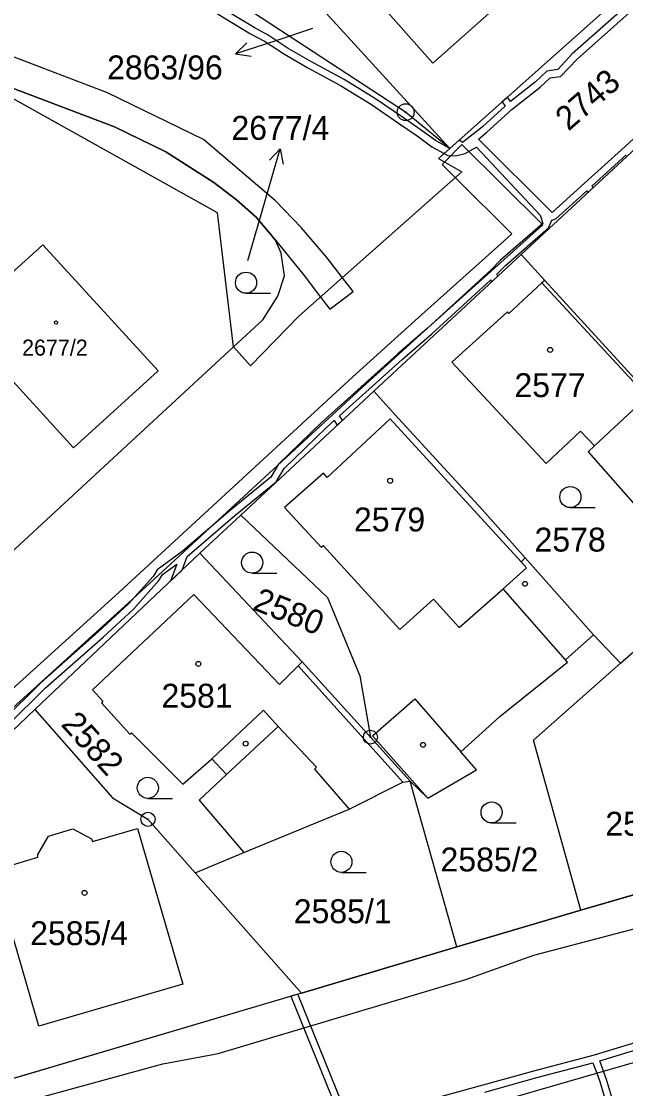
# Model space of a CAD drawing. Extents: x -644096 to -634268, y -1141430 to -1133463.
# Drawn here: x -639634.9 to -639592, y -1138632.6 to -1138556.7 of the extents above; entities that cross this region are included whole.
import ezdxf

# ---------------------------------------------------------------- set-up
doc = ezdxf.new("R2010")
doc.units = 0
for name, color, linetype in [('_CIVIL_CONSTRUCTION', 7, 'Continuous'), ('B_Hranice _3D', 7, 'Continuous'), ('M_Svah_Nasyp', 7, 'Continuous'), ('M_Svah_Zarez', 7, 'Continuous'), ('svrsek_osa_sjezdy', 7, 'Continuous'), ('svrsek_osa_terminal_VRT', 7, 'Continuous'), ('svrsek_osa_VRT', 7, 'Continuous'), ('svrsek_popisy_VRT', 7, 'Continuous'), ('terminal_VRT', 7, 'Continuous')]:
    doc.layers.add(name, color=color, linetype=linetype)

msp = doc.modelspace()

# ---------------------------------------------------------------- linework, layer by layer
at = {"layer": '_CIVIL_CONSTRUCTION'}
for centre, radius in [((-639607.63, -1138563.15), 0.6), ((-639607.63, -1138563.15), 0.0364), ((-639610.13, -1138607.58), 0.5), ((-639610.13, -1138607.58), 0.0303), ((-639625.94, -1138613.42), 0.5), ((-639625.94, -1138613.42), 0.0303)]:
    msp.add_circle(centre, radius, dxfattribs=at)
at = {"layer": 'B_Hranice _3D'}
for points in [[(-639658.11, -1138556.23), (-639639.64, -1138559.9), (-639628.33, -1138564.19), (-639624.68, -1138565.97), (-639621.26, -1138568.15), (-639619.65, -1138569.37), (-639618.26, -1138570.61), (-639616.87, -1138572.24), (-639614.84, -1138574.75), (-639613.67, -1138576.29), (-639613.01, -1138577.16), (-639611.37, -1138575.9), (-639612.12, -1138574.92), (-639613.24, -1138573.47), (-639615.04, -1138571.37), (-639616.88, -1138569.46), (-639622, -1138565.1), (-639628.82, -1138561.77), (-639635.75, -1138559.11), (-639643.38, -1138556.94), (-639667.92, -1138552.22)], [(-639578.14, -1138552.92), (-639582.84, -1138557.07), (-639585.31, -1138559.34), (-639587.95, -1138561.84), (-639592.29, -1138565.82), (-639594.91, -1138568.2), (-639597.21, -1138570.28), (-639602.45, -1138565.07), (-639601.85, -1138564.58), (-639600.07, -1138562.94), (-639598.08, -1138561.38), (-639597.36, -1138560.7), (-639596.62, -1138560.6), (-639595.44, -1138559.37), (-639590.01, -1138554.53)], [(-639590.43, -1138554.23), (-639595.8, -1138559.01), (-639596.82, -1138560.12), (-639597.59, -1138560.22)], [(-639621.62, -1138555.77), (-639618.65, -1138557.57), (-639617.65, -1138558.1), (-639616.23, -1138559.03), (-639614.57, -1138560), (-639612.27, -1138561.26), (-639610.06, -1138562.61), (-639608.13, -1138563.93), (-639606.81, -1138564.83), (-639605.76, -1138565.6), (-639604.89, -1138566.09), (-639604.63, -1138566.23), (-639604.09, -1138566.24), (-639603.4, -1138566.09), (-639602.6, -1138565.64), (-639598.06, -1138570.46), (-639597.89, -1138571.07), (-639600.88, -1138573.68), (-639601.56, -1138574.36), (-639606.1, -1138578.53), (-639608.21, -1138580.35), (-639613.61, -1138585.22), (-639616.67, -1138588.16), (-639617.22, -1138589.09), (-639620.08, -1138591.44)], [(-639597.59, -1138560.22), (-639598.4, -1138561), (-639600.18, -1138562.39), (-639600.4, -1138562.09), (-639600.78, -1138562.42), (-639600.56, -1138562.72), (-639602.17, -1138564.2), (-639603.59, -1138565.3), (-639603.82, -1138565.13), (-639604.49, -1138565.73), (-639605.5, -1138565.16), (-639606.53, -1138564.43), (-639607.85, -1138563.51), (-639609.78, -1138562.19), (-639612.01, -1138560.82), (-639614.33, -1138559.56), (-639615.97, -1138558.61), (-639617.39, -1138557.68), (-639618.39, -1138557.13), (-639621.36, -1138555.35)], [(-639641.76, -1138611.1), (-639627.33, -1138598.04), (-639617.93, -1138589.36), (-639610.71, -1138582.71), (-639606.3, -1138578.69), (-639599.97, -1138573.03), (-639597.88, -1138571.16), (-639603.63, -1138565.45), (-639604.86, -1138566.7), (-639605.03, -1138566.87), (-639604.09, -1138567.81), (-639600.08, -1138571.8), (-639600.63, -1138572.29), (-639606.96, -1138577.95), (-639611.39, -1138581.97), (-639618.61, -1138588.62), (-639628.01, -1138597.3)], [(-639635.92, -1138606.75), (-639633.22, -1138604.07), (-639629.13, -1138600.48), (-639626.97, -1138598.47), (-639625.17, -1138596.45), (-639624.91, -1138596.02), (-639623.89, -1138595.28), (-639624.34, -1138596.49), (-639623.51, -1138595.7), (-639623.15, -1138594.74), (-639619.76, -1138591.82), (-639616.84, -1138589.43), (-639616.27, -1138588.48), (-639613.27, -1138585.58), (-639612.7, -1138585.07), (-639612.49, -1138585.4), (-639612.11, -1138585.05), (-639612.32, -1138584.73), (-639607.87, -1138580.73), (-639605.76, -1138578.91), (-639601.58, -1138575.06), (-639601.56, -1138575.24), (-639601.11, -1138574.82), (-639601.13, -1138574.63), (-639600.54, -1138574.04), (-639597.47, -1138571.37), (-639597.25, -1138570.82), (-639596.95, -1138570.72), (-639594.76, -1138568.75), (-639594.67, -1138568.85), (-639594.3, -1138568.51), (-639594.39, -1138568.41), (-639591.95, -1138566.18)], [(-639636.06, -1138634.3), (-639634.04, -1138633.31), (-639624.89, -1138630.8), (-639620.95, -1138630.07), (-639603.36, -1138624.81), (-639598.51, -1138623.07), (-639582.86, -1138618.95), (-639554.59, -1138610.51), (-639542.49, -1138606.71), (-639532.13, -1138603.17), (-639523.43, -1138599.72), (-639503.23, -1138590.28), (-639493.08, -1138586.17)], [(-639498.99, -1138586.56), (-639513.43, -1138593.01), (-639522.91, -1138596.98), (-639524.57, -1138597.67), (-639533.41, -1138601.31), (-639536.57, -1138602.39), (-639543.26, -1138604.42), (-639551.43, -1138607.04), (-639555.39, -1138608.28), (-639566.35, -1138611.47), (-639568.99, -1138612.24), (-639574.69, -1138613.9), (-639595.17, -1138619.87), (-639603.99, -1138622.49), (-639615.04, -1138625.77), (-639637.75, -1138632.51)], [(-639620.08, -1138591.44), (-639623.52, -1138594.39), (-639625.29, -1138595.68), (-639625.57, -1138596.15), (-639627.33, -1138598.11), (-639629.47, -1138600.1), (-639633.56, -1138603.71), (-639636.26, -1138606.39)], [(-639628.01, -1138597.3), (-639642.44, -1138610.36), (-639646.98, -1138614.51)], [(-639544.79, -1138615.76), (-639545.43, -1138616.39), (-639546.02, -1138616.77), (-639546.4, -1138616.74), (-639546.76, -1138616.71), (-639550.78, -1138618), (-639554.66, -1138619.05), (-639560.3, -1138620.49), (-639567.96, -1138622.71), (-639573.14, -1138624.16), (-639577.64, -1138625.42), (-639579.66, -1138625.97), (-639585.28, -1138627.53), (-639588.31, -1138628.43), (-639590.19, -1138628.95), (-639594.23, -1138630.18), (-639598.45, -1138631.29), (-639602.15, -1138632.33), (-639607.83, -1138633.88)], [(-639592.51, -1138634.76), (-639593.35, -1138631.91), (-639593.56, -1138631.33), (-639593.84, -1138630.58), (-639590.05, -1138629.43), (-639588.41, -1138628.98), (-639588.19, -1138629.78), (-639588.04, -1138630.3), (-639587.1, -1138633.22)], [(-639602.01, -1138632.81), (-639598.31, -1138631.77), (-639594.32, -1138630.72), (-639594.05, -1138631.47), (-639593.83, -1138632.07), (-639592.99, -1138634.89)]]:
    msp.add_lwpolyline(points, dxfattribs=at)
msp.add_lwpolyline([(-639615.78, -1138625.99), (-639610.66, -1138638.62), (-639610.2, -1138638.43), (-639615.3, -1138625.85)], close=True, dxfattribs=at)
at = {"layer": 'M_Svah_Nasyp'}
for p, q in [((-639612.46, -1138552.02), (-639605.69, -1138559.66)), ((-639605.69, -1138559.66), (-639599.67, -1138554.3)), ((-639597.95, -1138575.27), (-639589.7, -1138584.2)), ((-639591.47, -1138584.3), (-639594.21, -1138586.86)), ((-639608.73, -1138584.94), (-639613.21, -1138589.13)), ((-639599.42, -1138595.11), (-639608.73, -1138584.94)), ((-639613.47, -1138588.8), (-639616.23, -1138591.24)), ((-639613.21, -1138589.13), (-639613.47, -1138588.8)), ((-639616.23, -1138591.24), (-639613.63, -1138594.07)), ((-639613.63, -1138594.07), (-639613.5, -1138593.95)), ((-639599.13, -1138594.84), (-639599.42, -1138595.11)), ((-639599.42, -1138595.11), (-639599.03, -1138595.54)), ((-639600.7, -1138597.04), (-639599.03, -1138595.54)), ((-639596.28, -1138602.07), (-639600.7, -1138597.04)), ((-639615.26, -1138602.51), (-639607.84, -1138610.78)), ((-639621.39, -1138609.13), (-639617.74, -1138605.67)), ((-639617.74, -1138605.67), (-639616.68, -1138606.81)), ((-639616.68, -1138606.81), (-639620.36, -1138610.24)), ((-639616.68, -1138606.81), (-639613.96, -1138609.72)), ((-639609.99, -1138607.49), (-639606.06, -1138611.91)), ((-639613.96, -1138609.72), (-639614.11, -1138609.86)), ((-639614.11, -1138609.86), (-639611.65, -1138612.69))]:
    msp.add_line(p, q, dxfattribs=at)
for points in [[(-639605.64, -1138597.77), (-639608.05, -1138599.92), (-639613.5, -1138593.95)], [(-639605.64, -1138597.77), (-639603.82, -1138599.78), (-639600.7, -1138597.04)], [(-639609.99, -1138607.49), (-639606.97, -1138604.85), (-639603.7, -1138608.63)]]:
    msp.add_lwpolyline(points, dxfattribs=at)
at = {"layer": 'M_Svah_Zarez'}
for centre, radius in [((-639632.475, -1138578.109), 0.117), ((-639597.367, -1138580.049), 0.175), ((-639608.727, -1138589.349), 0.175), ((-639599.147, -1138596.679), 0.175), ((-639622.357, -1138602.369), 0.175), ((-639618.997, -1138608.039), 0.175), ((-639606.397, -1138608.129), 0.175), ((-639630.447, -1138618.649), 0.175)]:
    msp.add_circle(centre, radius, dxfattribs=at)
at = {"layer": 'svrsek_osa_sjezdy'}
for p, q in [((-639618.973, -1138576.02), (-639617.223, -1138576.02)), ((-639595.923, -1138591.26), (-639594.173, -1138591.26)), ((-639618.533, -1138595.92), (-639616.783, -1138595.92)), ((-639625.953, -1138611.93), (-639624.203, -1138611.93)), ((-639601.523, -1138613.68), (-639599.773, -1138613.68)), ((-639612.193, -1138617.19), (-639610.443, -1138617.19))]:
    msp.add_line(p, q, dxfattribs=at)
for centre in [(-639618.973, -1138575.27), (-639595.923, -1138590.51), (-639618.533, -1138595.17), (-639625.953, -1138611.18), (-639601.523, -1138612.93), (-639612.193, -1138616.44)]:
    msp.add_circle(centre, 0.75, dxfattribs=at)
at = {"layer": 'svrsek_osa_terminal_VRT'}
msp.add_arc((-642050.261, -1145189.597), 8802.25, 41.4131519, 75.3170489, dxfattribs=at)
at = {"layer": 'svrsek_popisy_VRT'}
for p, q in [((-639614.26, -1138557.21), (-639616.86, -1138558.07)), ((-639616.86, -1138558.07), (-639619.714, -1138558.997)), ((-639619.714, -1138558.997), (-639618.916, -1138558.212)), ((-639619.714, -1138558.997), (-639618.607, -1138559.164)), ((-639617.37, -1138568.63), (-639616.543, -1138565.745)), ((-639616.543, -1138565.745), (-639617.3, -1138566.57)), ((-639616.543, -1138565.745), (-639616.338, -1138566.846)), ((-639618.84, -1138573.7), (-639617.37, -1138568.63))]:
    msp.add_line(p, q, dxfattribs=at)
at = {"layer": 'terminal_VRT'}
for p, q in [((-639615.47, -1138553.71), (-639604.49, -1138565.73)), ((-639604.49, -1138565.73), (-639593.46, -1138555.9)), ((-639585.65, -1138560.49), (-639599.43, -1138573.26)), ((-639599.43, -1138573.26), (-639609.9, -1138582.99)), ((-639599.43, -1138573.26), (-639597.73, -1138575.11)), ((-639637.64, -1138596.27), (-639619.86, -1138579.83)), ((-639609.9, -1138582.99), (-639619.35, -1138591.8)), ((-639619.35, -1138591.8), (-639622.25, -1138594.51)), ((-639622.25, -1138594.51), (-639633.98, -1138605.62)), ((-639622.25, -1138594.51), (-639614.98, -1138602.23)), ((-639592.36, -1138602.33), (-639588.9, -1138599.27)), ((-639594.28, -1138600.3), (-639592.36, -1138602.33)), ((-639614.98, -1138602.23), (-639610.13, -1138607.58)), ((-639645.23, -1138616.27), (-639633.98, -1138605.62)), ((-639610.13, -1138607.58), (-639607.3, -1138610.71)), ((-639595.17, -1138619.87), (-639574.69, -1138613.9)), ((-639622.58, -1138617.23), (-639619.12, -1138615.79)), ((-639622.58, -1138617.23), (-639615.04, -1138625.77)), ((-639603.99, -1138622.49), (-639595.17, -1138619.87)), ((-639615.04, -1138625.77), (-639603.99, -1138622.49)), ((-639615.04, -1138625.77), (-639637.75, -1138632.51))]:
    msp.add_line(p, q, dxfattribs=at)
for points in [[(-639604.49, -1138565.73), (-639607.63, -1138563.15), (-639619.59, -1138555.32)], [(-639619.86, -1138579.83), (-639621, -1138570.3), (-639639.64, -1138559.9)], [(-639619.86, -1138579.83), (-639617.78, -1138577.9), (-639616.7, -1138576.23), (-639616.24, -1138574.78), (-639616.47, -1138573.18), (-639616.87, -1138572.24), (-639618.26, -1138570.61), (-639619.65, -1138569.37), (-639621.26, -1138568.15), (-639624.68, -1138565.97), (-639628.33, -1138564.19), (-639639.64, -1138559.9)], [(-639420.67, -1138563.16), (-639420.77, -1138562.15), (-639453.01, -1138577.21), (-639479.01, -1138589.5), (-639514.61, -1138604.87), (-639530.15, -1138610.96), (-639554.65, -1138619.67), (-639587.03, -1138629.44), (-639631.61, -1138642.35), (-639671.45, -1138653.1), (-639676.11, -1138654.27)], [(-639604.49, -1138565.73), (-639605.29, -1138566.45), (-639603.63, -1138567.4), (-639615.21, -1138577.65), (-639618.66, -1138581.17), (-639619.86, -1138579.83)], [(-639638.03, -1138582.1), (-639642.04, -1138577.68), (-639639.22, -1138575.12), (-639637.93, -1138576.65), (-639633.41, -1138572.58), (-639625.21, -1138581.54), (-639631.23, -1138587.01), (-639636.77, -1138580.95), (-639638.03, -1138582.1)], [(-639597.73, -1138575.11), (-639597.95, -1138575.27), (-639600.29, -1138577.46), (-639600.39, -1138577.35), (-639604.35, -1138580.93), (-639597.64, -1138588.12), (-639595.21, -1138585.82), (-639594.21, -1138586.86), (-639594.67, -1138587.29), (-639588.18, -1138594.66), (-639585.46, -1138592.2), (-639583.55, -1138590.59)], [(-639597.73, -1138575.11), (-639589.54, -1138584.06), (-639583.55, -1138590.59)], [(-639609.9, -1138582.99), (-639608.4, -1138584.63), (-639602.2, -1138591.39), (-639599.13, -1138594.84), (-639594.28, -1138600.3)], [(-639619.35, -1138591.8), (-639613.19, -1138597.64), (-639610.88, -1138603.22), (-639610.13, -1138607.58)], [(-639614.98, -1138602.23), (-639615.26, -1138602.51), (-639616.6, -1138603.83), (-639622.68, -1138597.44), (-639629.87, -1138604.21), (-639629.14, -1138605.03), (-639629.25, -1138605.13), (-639627.22, -1138607.37), (-639627.11, -1138607.27), (-639623.47, -1138610.92), (-639621.39, -1138609.13), (-639620.36, -1138610.24), (-639622.31, -1138612.05), (-639619.12, -1138615.79)], [(-639607.3, -1138610.71), (-639606.06, -1138611.91), (-639602.59, -1138609.9), (-639603.7, -1138608.63), (-639600.93, -1138606.12), (-639596.13, -1138602.25), (-639596.28, -1138602.07), (-639594.28, -1138600.3)], [(-639595.17, -1138619.87), (-639598.55, -1138607.8), (-639592.36, -1138602.33)], [(-639633.98, -1138605.62), (-639628.46, -1138611.9), (-639625.94, -1138613.42), (-639622.58, -1138617.23)], [(-639619.12, -1138615.79), (-639611.65, -1138612.69), (-639607.84, -1138610.78), (-639607.3, -1138610.71)], [(-639603.99, -1138622.49), (-639606.66, -1138613), (-639607.3, -1138610.71)], [(-639623.47, -1138625.14), (-639633.69, -1138628.12), (-639636.91, -1138617.06), (-639633.77, -1138616.12), (-639633.77, -1138615.93), (-639633.01, -1138614.61), (-639631.28, -1138614.1), (-639629.96, -1138614.8), (-639629.88, -1138614.99), (-639626.69, -1138614.08), (-639623.47, -1138625.14)]]:
    msp.add_lwpolyline(points, dxfattribs=at)

# ---------------------------------------------------------------- texts
at = {"layer": 'svrsek_osa_VRT'}
for s, height, p in [('2863/96', 1.7, (-639628.846, -1138560.815)), ('2677/4', 1.7, (-639620.01, -1138565.115)), ('2677/2', 1.14, (-639634.884, -1138580.455)), ('2577', 1.7, (-639599.9, -1138583.405)), ('2579', 1.7, (-639611.3, -1138592.955)), ('2578', 1.7, (-639598.47, -1138594.385)), ('2581', 1.7, (-639624.98, -1138605.485)), ('2587', 1.7, (-639593.44, -1138614.585)), ('2585/2', 1.7, (-639605.15, -1138617.125)), ('2585/1', 1.7, (-639615.58, -1138620.805)), ('2585/4', 1.7, (-639634.31, -1138622.365))]:
    msp.add_text(s, height=height, dxfattribs=at).set_placement(p)
for s, rotation, p in [('2743', 41, (-639596.061, -1138564.54)), ('2580', 338, (-639618.579, -1138598.474)), ('2582', 312, (-639632.185, -1138606.704))]:
    msp.add_text(s, height=1.7, rotation=rotation, dxfattribs=at).set_placement(p)

doc.saveas('drawing.dxf')
